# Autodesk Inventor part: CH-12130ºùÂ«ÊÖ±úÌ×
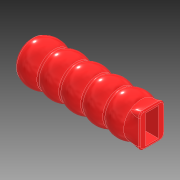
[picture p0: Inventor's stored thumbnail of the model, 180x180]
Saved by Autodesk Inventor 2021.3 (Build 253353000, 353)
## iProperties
Created: 2020-03
Part Number: CH-12130ºùÂ«ÊÖ±úÌ×
Material: Ogólny
Document SubType Name: Modeling
Designer: Przemyslaw Krecisz
Density: 1 g/cm^3
Appearance: Jasnoczerwona
Author: Przemyslaw Krecisz
Revision Number: ÈÎºÎ
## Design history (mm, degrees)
feature "ÇÐ³ý-À­Éì1"
node "Bryła1"
